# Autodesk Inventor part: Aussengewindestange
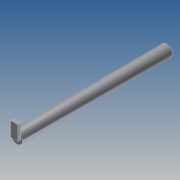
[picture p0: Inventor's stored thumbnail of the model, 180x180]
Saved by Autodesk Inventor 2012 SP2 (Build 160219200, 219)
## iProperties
Company: Caverion Deutschland GmbH - Krantz Komponenten
Created: 2013-10
Part Number: Aussengewindestange
Material: Standard
Document SubType Name: Modeling
Designer: Wsommer
Density: 1 g/cm^3
Mass: 5.12116 g
Surface Area: 27.2867 cm^2
Volume: 5.12116 cm^3
Author: Wsommer
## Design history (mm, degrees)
sketch "Skizze2"
  geometry: C1 r 4 at (0, 0)
  constraints: 1 centre point
  dimensions: "d0" = 8 diameter of C1
extrude "Extrusion1" new body sketch "Skizze2" distance "d1" = 100; taper "d2" = 0 deg
sketch "Skizze3"
  geometry: L1 (-2.14, -0.244)-(2.677, -0.244); L2 (2.677, -0.244)-(2.677, 9.577); L3 (2.677, 9.577)-(-2.14, 9.577); L4 (-2.14, 9.577)-(-2.14, -0.244)
  constraints: 8 end point, 2 parallel, 1 horizontal, 1 perpendicular
extrude "Extrusion2" join sketch "Skizze3" distance "d3" = 2; taper "d4" = 0 deg
node "Volumenkörper1"
node "Volumenkörpern"
node "Oberflächenkörpern"
